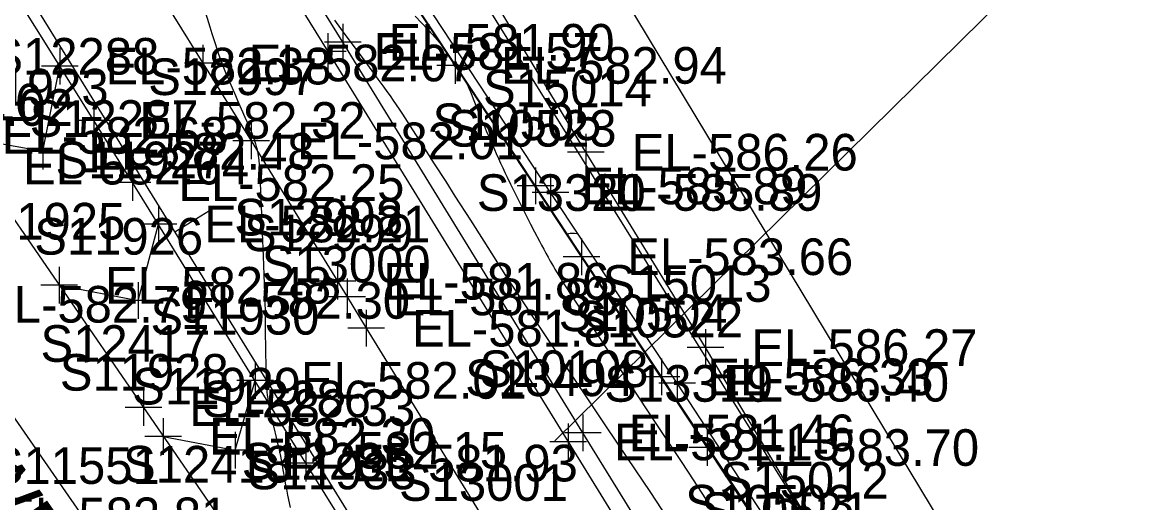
# Model space of a CAD drawing. Extents: x 1729869 to 1735532, y 648588 to 653771.
# Drawn here: x 1731784.2 to 1731905.1, y 651189.6 to 651242 of the extents above; entities that cross this region are included whole.
import ezdxf

# ---------------------------------------------------------------- set-up
doc = ezdxf.new("R2010")
doc.units = 0
for name, color, linetype in [('SURVEY - CENTERLINE - Preliminary', 7, 'Continuous'), ('SURVEY - CENTERLINE - Preliminary Text', 7, 'Continuous'), ('SURVEY - CONTOURS - Index with Text', 7, 'Continuous'), ('SURVEY - CONTOURS - Intermediate with optional Text', 7, 'Continuous'), ('SURVEY - DRAINAGE - Area Shapes', 7, 'Continuous'), ('SURVEY - DRAINAGE - Area Shapes Text', 7, 'Continuous'), ('SURVEY - DTM - Breaklines', 7, 'Continuous'), ('SURVEY - DTM - Breaklines - Points - Elevations', 7, 'Continuous'), ('SURVEY - DTM - Breaklines - Points - Locators', 7, 'Continuous'), ('SURVEY - DTM - Breaklines - Points - Numbers', 7, 'Continuous'), ('SURVEY - NON-TRANSPORTATION - Features', 7, 'Continuous'), ('SURVEY - PROPERTY - ROW Lines', 7, 'Continuous'), ('SURVEY - ROADSIDE BARRIERS - Points - Elevations', 7, 'Continuous'), ('SURVEY - ROADSIDE BARRIERS - Points - Locators', 7, 'Continuous'), ('SURVEY - ROADSIDE BARRIERS - Points - Numbers', 7, 'Continuous'), ('SURVEY - ROADSIDE BARRIERS with Text', 7, 'Continuous'), ('SURVEY - TRAFFIC CONTROL - Pavement Marking - Points - Elevations', 7, 'Continuous'), ('SURVEY - TRAFFIC CONTROL - Pavement Marking - Points - Locators', 7, 'Continuous'), ('SURVEY - TRAFFIC CONTROL - Pavement Marking - Points - Numbers', 7, 'Continuous'), ('SURVEY - TRAFFIC CONTROL - Pavement Marking with Text', 7, 'Continuous'), ('SURVEY - TRANSPORTATION - Features', 7, 'Continuous'), ('SURVEY - TRANSPORTATION - Features - Points - Elevations', 7, 'Continuous'), ('SURVEY - TRANSPORTATION - Features - Points - Locators', 7, 'Continuous'), ('SURVEY - TRANSPORTATION - Features - Points - Numbers', 7, 'Continuous'), ('SURVEY - TRANSPORTATION - Roads', 7, 'Continuous'), ('SURVEY - TRANSPORTATION - Roads - Points - Elevations', 7, 'Continuous'), ('SURVEY - TRANSPORTATION - Roads - Points - Locators', 7, 'Continuous'), ('SURVEY - TRANSPORTATION - Roads - Points - Numbers', 7, 'Continuous'), ('SURVEY - TRANSPORTATION - Roads Text', 7, 'Continuous')]:
    doc.layers.add(name, color=color, linetype=linetype)

msp = doc.modelspace()

# ---------------------------------------------------------------- linework, layer by layer
at = {"layer": 'SURVEY - CENTERLINE - Preliminary'}
msp.add_line((1731573.18, 651587.85), (1731916.82, 651031.47), dxfattribs=at)
at = {"layer": 'SURVEY - CENTERLINE - Preliminary Text'}
msp.add_line((1731800.91, 651219.14), (1731805.17, 651221.76), dxfattribs=at)
at = {"layer": 'SURVEY - CONTOURS - Index with Text'}
msp.add_lwpolyline([(1731873.75, 651173.51), (1731872.52, 651175.37), (1731868.45, 651181.52), (1731857.7, 651197.73), (1731854.03, 651203.28), (1731843.41, 651219.37), (1731831.74, 651237.08), (1731825.48, 651246.56)], dxfattribs=at)
at = {"layer": 'SURVEY - CONTOURS - Intermediate with optional Text'}
for points in [[(1731824.46, 651248.01), (1731830.68, 651238.62), (1731833.12, 651234.93), (1731846.22, 651215.06), (1731857.86, 651197.43), (1731860.74, 651193.07), (1731871.77, 651176.43), (1731873.87, 651173.26), (1731885.25, 651156), (1731886.91, 651153.48), (1731889.06, 651150.26), (1731900.4, 651133.24), (1731902.64, 651129.86), (1731911.4, 651116.66), (1731922.79, 651099.48), (1731932.82, 651084.33)], [(1731804.12, 651243.53), (1731804.73, 651241.52), (1731804.95, 651240.79), (1731805.12, 651240.26), (1731805.3, 651239.7), (1731805.49, 651239.13), (1731805.66, 651238.64), (1731805.8, 651238.24), (1731805.96, 651237.82), (1731806.04, 651237.6), (1731806.24, 651237.09), (1731806.45, 651236.55), (1731806.68, 651236), (1731806.91, 651235.44), (1731807.16, 651234.87), (1731807.52, 651234.02), (1731807.76, 651233.49), (1731808.56, 651231.68), (1731808.81, 651231.11), (1731809.05, 651230.55), (1731809.3, 651229.93), (1731809.46, 651229.53), (1731809.57, 651229.23), (1731809.65, 651228.98), (1731809.73, 651228.74), (1731809.8, 651228.48), (1731809.87, 651228.23), (1731809.93, 651227.96), (1731810.01, 651227.49), (1731810.08, 651226.98), (1731810.13, 651226.46), (1731810.17, 651225.93), (1731810.2, 651225.39), (1731810.23, 651224.65), (1731810.27, 651223.47), (1731810.32, 651222.08), (1731810.36, 651220.88), (1731810.44, 651219.04), (1731810.55, 651216.51), (1731810.64, 651214.47), (1731810.68, 651213.47), (1731810.71, 651212.43), (1731810.74, 651211.43), (1731810.76, 651210.47), (1731810.78, 651209.65), (1731810.78, 651208.64), (1731810.79, 651207.57), (1731810.8, 651207.07), (1731810.82, 651206.08), (1731810.86, 651204.48), (1731810.9, 651203.05), (1731810.91, 651202.72), (1731810.93, 651202.38), (1731810.95, 651202.03), (1731810.97, 651201.68), (1731811.01, 651201.32), (1731811.05, 651200.95), (1731811.11, 651200.57), (1731811.18, 651200.13), (1731811.27, 651199.68), (1731811.37, 651199.21), (1731811.48, 651198.74), (1731811.72, 651197.78), (1731811.98, 651196.71), (1731812.1, 651196.19), (1731812.22, 651195.66), (1731812.34, 651195.15), (1731812.44, 651194.65), (1731812.52, 651194.26), (1731812.59, 651193.89), (1731812.71, 651193.17), (1731812.88, 651192.22), (1731812.97, 651191.72), (1731813.1, 651191.06), (1731813.23, 651190.39), (1731813.51, 651189.05)], [(1731854.76, 651187.85), (1731852.8, 651190.81), (1731850.39, 651194.39), (1731847.98, 651197.98), (1731842.64, 651205.96), (1731840.14, 651209.7), (1731839.23, 651211.07), (1731838.31, 651212.47), (1731837.68, 651213.42), (1731837.07, 651214.37), (1731834.68, 651218.12), (1731833.22, 651220.42), (1731831.53, 651223.06), (1731830.53, 651224.64), (1731829.28, 651226.58), (1731827.86, 651228.82), (1731827.24, 651229.78), (1731826.32, 651231.21), (1731825.79, 651232.01), (1731825.44, 651232.54), (1731825.12, 651233.02), (1731824.78, 651233.5), (1731824.45, 651233.98), (1731824.1, 651234.47), (1731823.75, 651234.95), (1731823.13, 651235.81), (1731821.5, 651238.02), (1731819.51, 651240.71), (1731818.37, 651242.27)], [(1731827.15, 651242.71), (1731828.52, 651241.25), (1731828.79, 651240.96), (1731829.05, 651240.68), (1731829.3, 651240.4), (1731829.55, 651240.12), (1731829.79, 651239.85), (1731830.02, 651239.57), (1731830.25, 651239.26), (1731830.96, 651238.19), (1731832.52, 651235.83), (1731832.69, 651235.54), (1731832.86, 651235.19), (1731833.02, 651234.82), (1731833.18, 651234.45), (1731833.34, 651234.06), (1731833.5, 651233.67), (1731834.23, 651231.86), (1731834.45, 651231.31), (1731834.68, 651230.75), (1731834.92, 651230.18), (1731835.15, 651229.62), (1731835.49, 651228.84), (1731835.8, 651228.15), (1731836.01, 651227.69), (1731836.24, 651227.17), (1731836.48, 651226.66), (1731836.72, 651226.14), (1731836.96, 651225.63), (1731837.2, 651225.13), (1731837.57, 651224.36), (1731838.08, 651223.33), (1731838.91, 651221.66), (1731839.38, 651220.72), (1731839.76, 651219.98), (1731840.19, 651219.14), (1731840.72, 651218.14), (1731840.95, 651217.69), (1731841.19, 651217.25), (1731841.42, 651216.81), (1731841.66, 651216.37), (1731841.91, 651215.94), (1731842.08, 651215.64), (1731842.25, 651215.35), (1731842.42, 651215.06), (1731842.59, 651214.77), (1731842.95, 651214.19), (1731843.21, 651213.77), (1731843.47, 651213.36), (1731843.74, 651212.94), (1731844.27, 651212.12), (1731844.92, 651211.14), (1731847.5, 651207.26), (1731848.96, 651205.04), (1731853.37, 651198.35), (1731856.04, 651194.29), (1731857.02, 651192.8), (1731861.62, 651185.74)], [(1731867.76, 651182.64), (1731855.88, 651200.54), (1731854.18, 651203.12), (1731851.31, 651207.48), (1731850.72, 651208.37), (1731850.35, 651208.92), (1731849.98, 651209.48), (1731849.59, 651210.05), (1731849.2, 651210.63), (1731848.76, 651211.27), (1731844.06, 651218.4), (1731843.8, 651218.85), (1731843.86, 651218.93), (1731843.95, 651218.97), (1731844.07, 651219), (1731844.22, 651219.01), (1731844.38, 651219), (1731844.56, 651218.99), (1731844.81, 651218.95), (1731844.94, 651218.94)]]:
    msp.add_lwpolyline(points, dxfattribs=at)
at = {"layer": 'SURVEY - DRAINAGE - Area Shapes'}
msp.add_lwpolyline([(1731977.01, 651015.71), (1731920.48, 650979.52), (1731672.57, 651339.39), (1731746.65, 651385.64)], close=True, dxfattribs=at)
at = {"layer": 'SURVEY - DRAINAGE - Area Shapes Text'}
msp.add_line((1732048.63, 651399.54), (1731842.39, 651196.32), dxfattribs=at)
at = {"layer": 'SURVEY - DTM - Breaklines'}
for points in [[(1732003.05, 650973.97), (1732003.58, 650974.31), (1731989.55, 650996.2), (1731978.61, 651014.1), (1731965.16, 651035.18), (1731951.94, 651056.41), (1731938.34, 651077.39), (1731924.59, 651098.27), (1731910.74, 651119.08), (1731897.04, 651139.99), (1731883.27, 651160.86), (1731869.45, 651181.7), (1731855.77, 651202.62), (1731841.94, 651223.45), (1731828.19, 651244.33), (1731813.14, 651266.45), (1731799.48, 651287.55), (1731797, 651291.32), (1731796.49, 651290.99), (1731796.24, 651290.84)], [(1731936.96, 651078.17), (1731923.15, 651099.07), (1731909.31, 651119.93), (1731895.46, 651140.77), (1731881.69, 651161.58), (1731867.87, 651182.52), (1731854.06, 651203.31), (1731840.29, 651224.16), (1731826.44, 651245.13), (1731812.64, 651265.98), (1731798.96, 651286.91), (1731796.49, 651290.99)], [(1731950.51, 651027.04), (1731924.23, 651069.54), (1731897.97, 651112.12), (1731871.74, 651154.65), (1731845.47, 651197.2), (1731819.24, 651239.84), (1731804.72, 651263.29), (1731803.1, 651262.29)]]:
    msp.add_lwpolyline(points, dxfattribs=at)
at = {"layer": 'SURVEY - DTM - Breaklines - Points - Locators'}
for p, q in [((1731819.24, 651241.84), (1731819.24, 651237.84)), ((1731821.24, 651239.84), (1731817.24, 651239.84)), ((1731845.8, 651229.84), (1731845.8, 651225.84)), ((1731847.8, 651227.84), (1731843.8, 651227.84)), ((1731840.29, 651226.16), (1731840.29, 651222.16)), ((1731841.94, 651225.45), (1731841.94, 651221.45)), ((1731842.29, 651224.16), (1731838.29, 651224.16)), ((1731843.94, 651223.45), (1731839.94, 651223.45)), ((1731858.87, 651208.51), (1731858.87, 651204.51)), ((1731860.87, 651206.51), (1731856.87, 651206.51)), ((1731854.06, 651205.31), (1731854.06, 651201.31)), ((1731855.77, 651204.62), (1731855.77, 651200.62)), ((1731856.06, 651203.31), (1731852.06, 651203.31)), ((1731857.77, 651202.62), (1731853.77, 651202.62)), ((1731845.47, 651199.2), (1731845.47, 651195.2)), ((1731847.47, 651197.2), (1731843.47, 651197.2))]:
    msp.add_line(p, q, dxfattribs=at)
at = {"layer": 'SURVEY - NON-TRANSPORTATION - Features'}
msp.add_lwpolyline([(1731952.26, 651084.15), (1731934.95, 651102.63), (1731917.56, 651121.06), (1731897.77, 651142.36), (1731884.55, 651163.59), (1731871.66, 651185.02), (1731858.87, 651206.51), (1731845.8, 651227.84), (1731832.89, 651249.26), (1731820.14, 651270.78), (1731807.11, 651292.12), (1731794.16, 651313.52), (1731781.3, 651334.98)], dxfattribs=at)
at = {"layer": 'SURVEY - PROPERTY - ROW Lines'}
msp.add_line((1731760.63, 651392.64), (1731907.34, 651149.68), dxfattribs=at)
at = {"layer": 'SURVEY - ROADSIDE BARRIERS - Points - Locators'}
for p, q in [((1731831.51, 651239.32), (1731831.51, 651235.32)), ((1731833.51, 651237.32), (1731829.51, 651237.32)), ((1731845.3, 651218.43), (1731845.3, 651214.43)), ((1731847.3, 651216.43), (1731843.3, 651216.43)), ((1731859.05, 651197.6), (1731859.05, 651193.6)), ((1731861.05, 651195.6), (1731857.05, 651195.6))]:
    msp.add_line(p, q, dxfattribs=at)
at = {"layer": 'SURVEY - ROADSIDE BARRIERS with Text'}
msp.add_lwpolyline([(1732003.04, 650973.97), (1731988.24, 650997.51), (1731985.96, 651001.17), (1731980.62, 651009.64), (1731978.24, 651013.36), (1731975.84, 651017.14), (1731972.56, 651022.26), (1731967.19, 651030.69), (1731963.96, 651035.95), (1731958.62, 651044.4), (1731947.92, 651061.36), (1731942.45, 651069.66), (1731928.64, 651090.56), (1731914.82, 651111.43), (1731900.53, 651133.04), (1731886.68, 651153.81), (1731872.91, 651174.69), (1731859.05, 651195.6), (1731845.3, 651216.43), (1731831.51, 651237.32), (1731817.64, 651258.22), (1731811.49, 651267.57), (1731801.26, 651282.77), (1731796.24, 651290.84)], dxfattribs=at)
msp.add_lwpolyline([(1732003.04, 650973.97), (1731988.24, 650997.51), (1731985.96, 651001.17), (1731980.62, 651009.64), (1731978.24, 651013.36), (1731975.84, 651017.14), (1731972.56, 651022.26), (1731967.19, 651030.69), (1731963.96, 651035.95), (1731958.62, 651044.4), (1731947.92, 651061.36), (1731942.45, 651069.66), (1731928.64, 651090.56), (1731914.82, 651111.43), (1731900.53, 651133.04), (1731886.68, 651153.81), (1731872.91, 651174.69), (1731859.05, 651195.6), (1731845.3, 651216.43), (1731831.51, 651237.32), (1731817.64, 651258.22), (1731811.49, 651267.57), (1731801.26, 651282.77), (1731796.24, 651290.84)], dxfattribs=at)
at = {"layer": 'SURVEY - TRAFFIC CONTROL - Pavement Marking - Points - Locators'}
for p, q in [((1731788.34, 651239.24), (1731788.34, 651235.24)), ((1731790.34, 651237.24), (1731786.34, 651237.24)), ((1731786.48, 651229.94), (1731786.48, 651225.94)), ((1731788.48, 651227.94), (1731784.48, 651227.94)), ((1731799.12, 651222), (1731799.12, 651218)), ((1731801.12, 651220), (1731797.12, 651220)), ((1731788.29, 651215.31), (1731788.29, 651211.31)), ((1731790.29, 651213.31), (1731786.29, 651213.31)), ((1731796.91, 651213.66), (1731796.91, 651209.66)), ((1731798.91, 651211.66), (1731794.91, 651211.66)), ((1731809.67, 651204.93), (1731809.67, 651200.93)), ((1731811.67, 651202.93), (1731807.67, 651202.93)), ((1731799.64, 651198.81), (1731799.64, 651194.81)), ((1731807.5, 651197.3), (1731807.5, 651193.3)), ((1731801.64, 651196.81), (1731797.64, 651196.81)), ((1731809.5, 651195.3), (1731805.5, 651195.3))]:
    msp.add_line(p, q, dxfattribs=at)
at = {"layer": 'SURVEY - TRAFFIC CONTROL - Pavement Marking with Text'}
for points in [[(1731857.64, 651091.06), (1731837.26, 651120.73), (1731836.13, 651122.38), (1731832.72, 651127.32), (1731810.05, 651160.27), (1731791.9, 651186.63), (1731774.76, 651211.24), (1731760.1, 651232.72), (1731745.39, 651254.16), (1731726.04, 651282.12), (1731719.23, 651292), (1731711.29, 651303.53), (1731710.16, 651305.18), (1731707.89, 651308.47), (1731686.32, 651339.76)], [(1731777.01, 651229.68), (1731786.48, 651227.94), (1731788.34, 651237.24)], [(1731788.29, 651213.31), (1731796.91, 651211.66), (1731799.12, 651220)], [(1731799.64, 651196.81), (1731807.5, 651195.3), (1731809.67, 651202.93)]]:
    msp.add_lwpolyline(points, dxfattribs=at)
at = {"layer": 'SURVEY - TRANSPORTATION - Features'}
msp.add_lwpolyline([(1731747.61, 651345.53), (1731775.27, 651303.84), (1731803.1, 651262.29), (1731817.63, 651238.84), (1731843.85, 651196.21), (1731870.12, 651153.66), (1731896.35, 651111.12), (1731922.61, 651068.55), (1731948.89, 651026.04)], dxfattribs=at)
at = {"layer": 'SURVEY - TRANSPORTATION - Features - Points - Locators'}
for p, q in [((1731817.63, 651240.84), (1731817.63, 651236.84)), ((1731819.63, 651238.84), (1731815.63, 651238.84)), ((1731843.85, 651198.21), (1731843.85, 651194.21)), ((1731845.85, 651196.21), (1731841.85, 651196.21))]:
    msp.add_line(p, q, dxfattribs=at)
at = {"layer": 'SURVEY - TRANSPORTATION - Roads'}
for points in [[(1731725.12, 651365.19), (1731752.42, 651320.93), (1731763.98, 651302.21), (1731768.18, 651295.4), (1731775.54, 651283.49), (1731779.75, 651276.69), (1731797.65, 651247.78), (1731803.97, 651237.58), (1731809.24, 651229.08), (1731818.68, 651213.75), (1731819.72, 651212.04), (1731821.81, 651208.63), (1731836.47, 651184.78), (1731846.98, 651167.76), (1731866.86, 651135.37), (1731893.09, 651092.81)], [(1731947.97, 650982.07), (1731938.27, 650997.22), (1731925.42, 651017.5), (1731920.09, 651025.96), (1731904.18, 651051.39), (1731902.04, 651054.77), (1731891.37, 651071.68), (1731878.7, 651092.07), (1731867.07, 651110.74), (1731853.23, 651132.75), (1731852.18, 651134.45), (1731850.07, 651137.85), (1731840.6, 651153.16), (1731838.5, 651156.56), (1731831.11, 651168.45), (1731825.81, 651176.93), (1731819.45, 651187.11), (1731815.23, 651193.9), (1731796.29, 651224.52), (1731792.05, 651231.31), (1731779.32, 651251.65), (1731771.89, 651263.52), (1731744.16, 651307.51), (1731731.33, 651327.79)], [(1731709.99, 651326.7), (1731729.32, 651298.73), (1731740.7, 651282.28), (1731779.33, 651226.32), (1731797.48, 651199.96), (1731806.55, 651186.78), (1731821.3, 651165.37), (1731838.33, 651140.67), (1731865.46, 651101.07), (1731884.81, 651073.12), (1731905.27, 651043.5), (1731908.68, 651038.56), (1731915.49, 651028.68), (1731924.57, 651015.51), (1731947.97, 650982.07)]]:
    msp.add_lwpolyline(points, dxfattribs=at)
at = {"layer": 'SURVEY - TRANSPORTATION - Roads - Points - Locators'}
for p, q in [((1731803.97, 651239.58), (1731803.97, 651235.58)), ((1731805.97, 651237.58), (1731801.97, 651237.58)), ((1731792.05, 651233.31), (1731792.05, 651229.31)), ((1731794.05, 651231.31), (1731790.05, 651231.31)), ((1731809.24, 651231.08), (1731809.24, 651227.08)), ((1731811.24, 651229.08), (1731807.24, 651229.08)), ((1731796.29, 651226.52), (1731796.29, 651222.52)), ((1731798.29, 651224.52), (1731794.29, 651224.52)), ((1731818.68, 651215.75), (1731818.68, 651211.75)), ((1731819.72, 651214.04), (1731819.72, 651210.04)), ((1731820.68, 651213.75), (1731816.68, 651213.75)), ((1731821.72, 651212.04), (1731817.72, 651212.04)), ((1731821.81, 651210.63), (1731821.81, 651206.63)), ((1731823.81, 651208.63), (1731819.81, 651208.63)), ((1731797.48, 651201.96), (1731797.48, 651197.96)), ((1731799.48, 651199.96), (1731795.48, 651199.96)), ((1731815.23, 651195.9), (1731815.23, 651191.9)), ((1731817.23, 651193.9), (1731813.23, 651193.9))]:
    msp.add_line(p, q, dxfattribs=at)

# ---------------------------------------------------------------- texts
at = {"layer": 'SURVEY - DTM - Breaklines - Points - Elevations'}
for s, p in [('EL-581.90', (1731824.24, 651237.84)), ('EL-586.26', (1731850.8, 651225.84)), ('EL-585.89', (1731845.29, 651222.16)), ('EL-585.89', (1731846.94, 651221.45)), ('EL-586.27', (1731863.87, 651204.51)), ('EL-586.33', (1731859.06, 651201.31)), ('EL-586.40', (1731860.77, 651200.62)), ('EL-581.46', (1731850.47, 651195.2))]:
    msp.add_text(s, height=4, dxfattribs=at).set_placement(p)
at = {"layer": 'SURVEY - DTM - Breaklines - Points - Numbers'}
for s, p in [('S15014', (1731834.56, 651232.84)), ('S10505', (1731829.05, 651229.16)), ('S10523', (1731830.7, 651228.45)), ('S15013', (1731847.63, 651211.51)), ('S10504', (1731842.82, 651208.31)), ('S10522', (1731844.53, 651207.62)), ('S10108', (1731834.18, 651202.2)), ('S15012', (1731860.42, 651190.02)), ('S10503', (1731856.63, 651187.52)), ('S10521', (1731858.37, 651186.7))]:
    msp.add_text(s, height=4, dxfattribs=at).set_placement(p)
at = {"layer": 'SURVEY - ROADSIDE BARRIERS - Points - Elevations'}
for s, p in [('EL-582.94', (1731836.51, 651235.32)), ('EL-583.66', (1731850.3, 651214.43)), ('EL-583.70', (1731864.05, 651193.6))]:
    msp.add_text(s, height=4, dxfattribs=at).set_placement(p)
at = {"layer": 'SURVEY - ROADSIDE BARRIERS - Points - Numbers'}
for s, p in [('S13320', (1731833.89, 651221.43)), ('S13319', (1731847.8, 651200.6))]:
    msp.add_text(s, height=4, dxfattribs=at).set_placement(p)
at = {"layer": 'SURVEY - TRAFFIC CONTROL - Pavement Marking - Points - Elevations'}
for s, p in [('EL-582.38', (1731793.34, 651235.24)), ('EL-583.02', (1731765.1, 651230.72)), ('EL-582.68', (1731782.01, 651227.68)), ('EL-582.48', (1731791.48, 651225.94)), ('EL-582.21', (1731804.12, 651218)), ('EL-582.48', (1731793.29, 651211.31)), ('EL-582.79', (1731779.76, 651209.24)), ('EL-582.30', (1731801.91, 651209.66)), ('EL-582.02', (1731814.67, 651200.93)), ('EL-582.30', (1731804.64, 651194.81)), ('EL-582.15', (1731812.5, 651193.3))]:
    msp.add_text(s, height=4, dxfattribs=at).set_placement(p)
at = {"layer": 'SURVEY - TRAFFIC CONTROL - Pavement Marking - Points - Numbers'}
for s, p in [('S11923', (1731775.24, 651232.94)), ('S11927', (1731787.88, 651225)), ('S11925', (1731777.06, 651218.31)), ('S11926', (1731785.56, 651216.66)), ('S11930', (1731798.25, 651207.93)), ('S11928', (1731788.35, 651201.81)), ('S11929', (1731796.25, 651200.3)), ('S11551', (1731780.82, 651191.63)), ('S11933', (1731808.87, 651191.04))]:
    msp.add_text(s, height=4, dxfattribs=at).set_placement(p)
at = {"layer": 'SURVEY - TRANSPORTATION - Features - Points - Elevations'}
for s, p in [('EL-581.57', (1731822.63, 651236.84)), ('EL-581.13', (1731848.85, 651194.21))]:
    msp.add_text(s, height=4, dxfattribs=at).set_placement(p)
at = {"layer": 'SURVEY - TRANSPORTATION - Features - Points - Numbers'}
msp.add_text('S13494', height=4, dxfattribs=at).set_placement((1731832.61, 651201.21))
at = {"layer": 'SURVEY - TRANSPORTATION - Roads - Points - Elevations'}
for s, p in [('EL-582.07', (1731808.97, 651235.58)), ('EL-582.32', (1731797.05, 651229.31)), ('EL-582.01', (1731814.24, 651227.08)), ('EL-582.64', (1731784.33, 651224.32)), ('EL-582.25', (1731801.29, 651222.52)), ('EL-581.86', (1731823.68, 651211.75)), ('EL-581.83', (1731824.72, 651210.04)), ('EL-581.81', (1731826.81, 651206.63)), ('EL-582.33', (1731802.48, 651197.96)), ('EL-581.93', (1731820.23, 651191.9)), ('EL-582.81', (1731782.06, 651186.14))]:
    msp.add_text(s, height=4, dxfattribs=at).set_placement(p)
at = {"layer": 'SURVEY - TRANSPORTATION - Roads - Points - Numbers'}
for s, p in [('S12288', (1731780.77, 651236.31)), ('S12997', (1731798, 651234.08)), ('S12416', (1731767.98, 651231.32)), ('S12287', (1731785.06, 651229.52)), ('S12998', (1731807.39, 651218.75)), ('S12999', (1731808.47, 651217.04)), ('S13000', (1731810.4, 651213.63)), ('S12417', (1731786.24, 651204.96)), ('S12286', (1731803.88, 651198.9)), ('S12418', (1731795.26, 651191.78)), ('S12285', (1731808.21, 651192.11)), ('S13001', (1731825.39, 651189.78))]:
    msp.add_text(s, height=4, dxfattribs=at).set_placement(p)
at = {"layer": 'SURVEY - TRANSPORTATION - Roads Text'}
msp.add_text('I-440 WEST BOUND (CONC.)', height=6, rotation=304.7545, dxfattribs=at).set_placement((1731765.64, 651210.02))

doc.saveas('drawing.dxf')
